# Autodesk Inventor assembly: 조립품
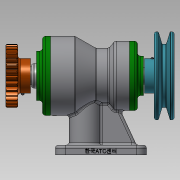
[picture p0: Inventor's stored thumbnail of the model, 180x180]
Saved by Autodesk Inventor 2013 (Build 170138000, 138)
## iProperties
Created: 2019-01
Part Number: 조립품
Document SubType Name: Assembly
Designer: hana-cad16
Author: hana-cad16
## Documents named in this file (15)
- C:\Documents and Settings\hana-cad16\바탕 화면\490107V1004\조립품.iam
- C:\Documents and Settings\hana-cad16\바탕 화면\490107V1004\V-벨트풀리.ipt
- C:\Documents and Settings\hana-cad16\바탕 화면\490107V1004\뒤커버.ipt
- C:\Documents and Settings\hana-cad16\바탕 화면\490107V1004\멈춤나사 M3.ipt
- C:\Documents and Settings\hana-cad16\바탕 화면\490107V1004\베어링 6203.ipt
- C:\Documents and Settings\hana-cad16\바탕 화면\490107V1004\베어링 6205.ipt
- C:\Documents and Settings\hana-cad16\바탕 화면\490107V1004\본체.ipt
- C:\Documents and Settings\hana-cad16\바탕 화면\490107V1004\볼트 M4.ipt
- C:\Documents and Settings\hana-cad16\바탕 화면\490107V1004\스퍼기어.ipt
- C:\Documents and Settings\hana-cad16\바탕 화면\490107V1004\앞커버.ipt
- C:\Documents and Settings\hana-cad16\바탕 화면\490107V1004\오일 실 17 30 8.ipt
- C:\Documents and Settings\hana-cad16\바탕 화면\490107V1004\오일 실 25 38 8.ipt
- C:\Documents and Settings\hana-cad16\바탕 화면\490107V1004\축.ipt
- C:\Documents and Settings\hana-cad16\바탕 화면\490107V1004\키 5 x 5 x 20.ipt
- C:\Documents and Settings\hana-cad16\바탕 화면\490107V1004\키 6 x 6 x 18.ipt
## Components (1 placed, 1 different names)
1. V-벨트풀리:1
